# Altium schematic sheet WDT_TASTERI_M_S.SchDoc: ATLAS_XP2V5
size 558 x 431 mm; Organization: IMP Automatika d.o.o.; Revision: V5
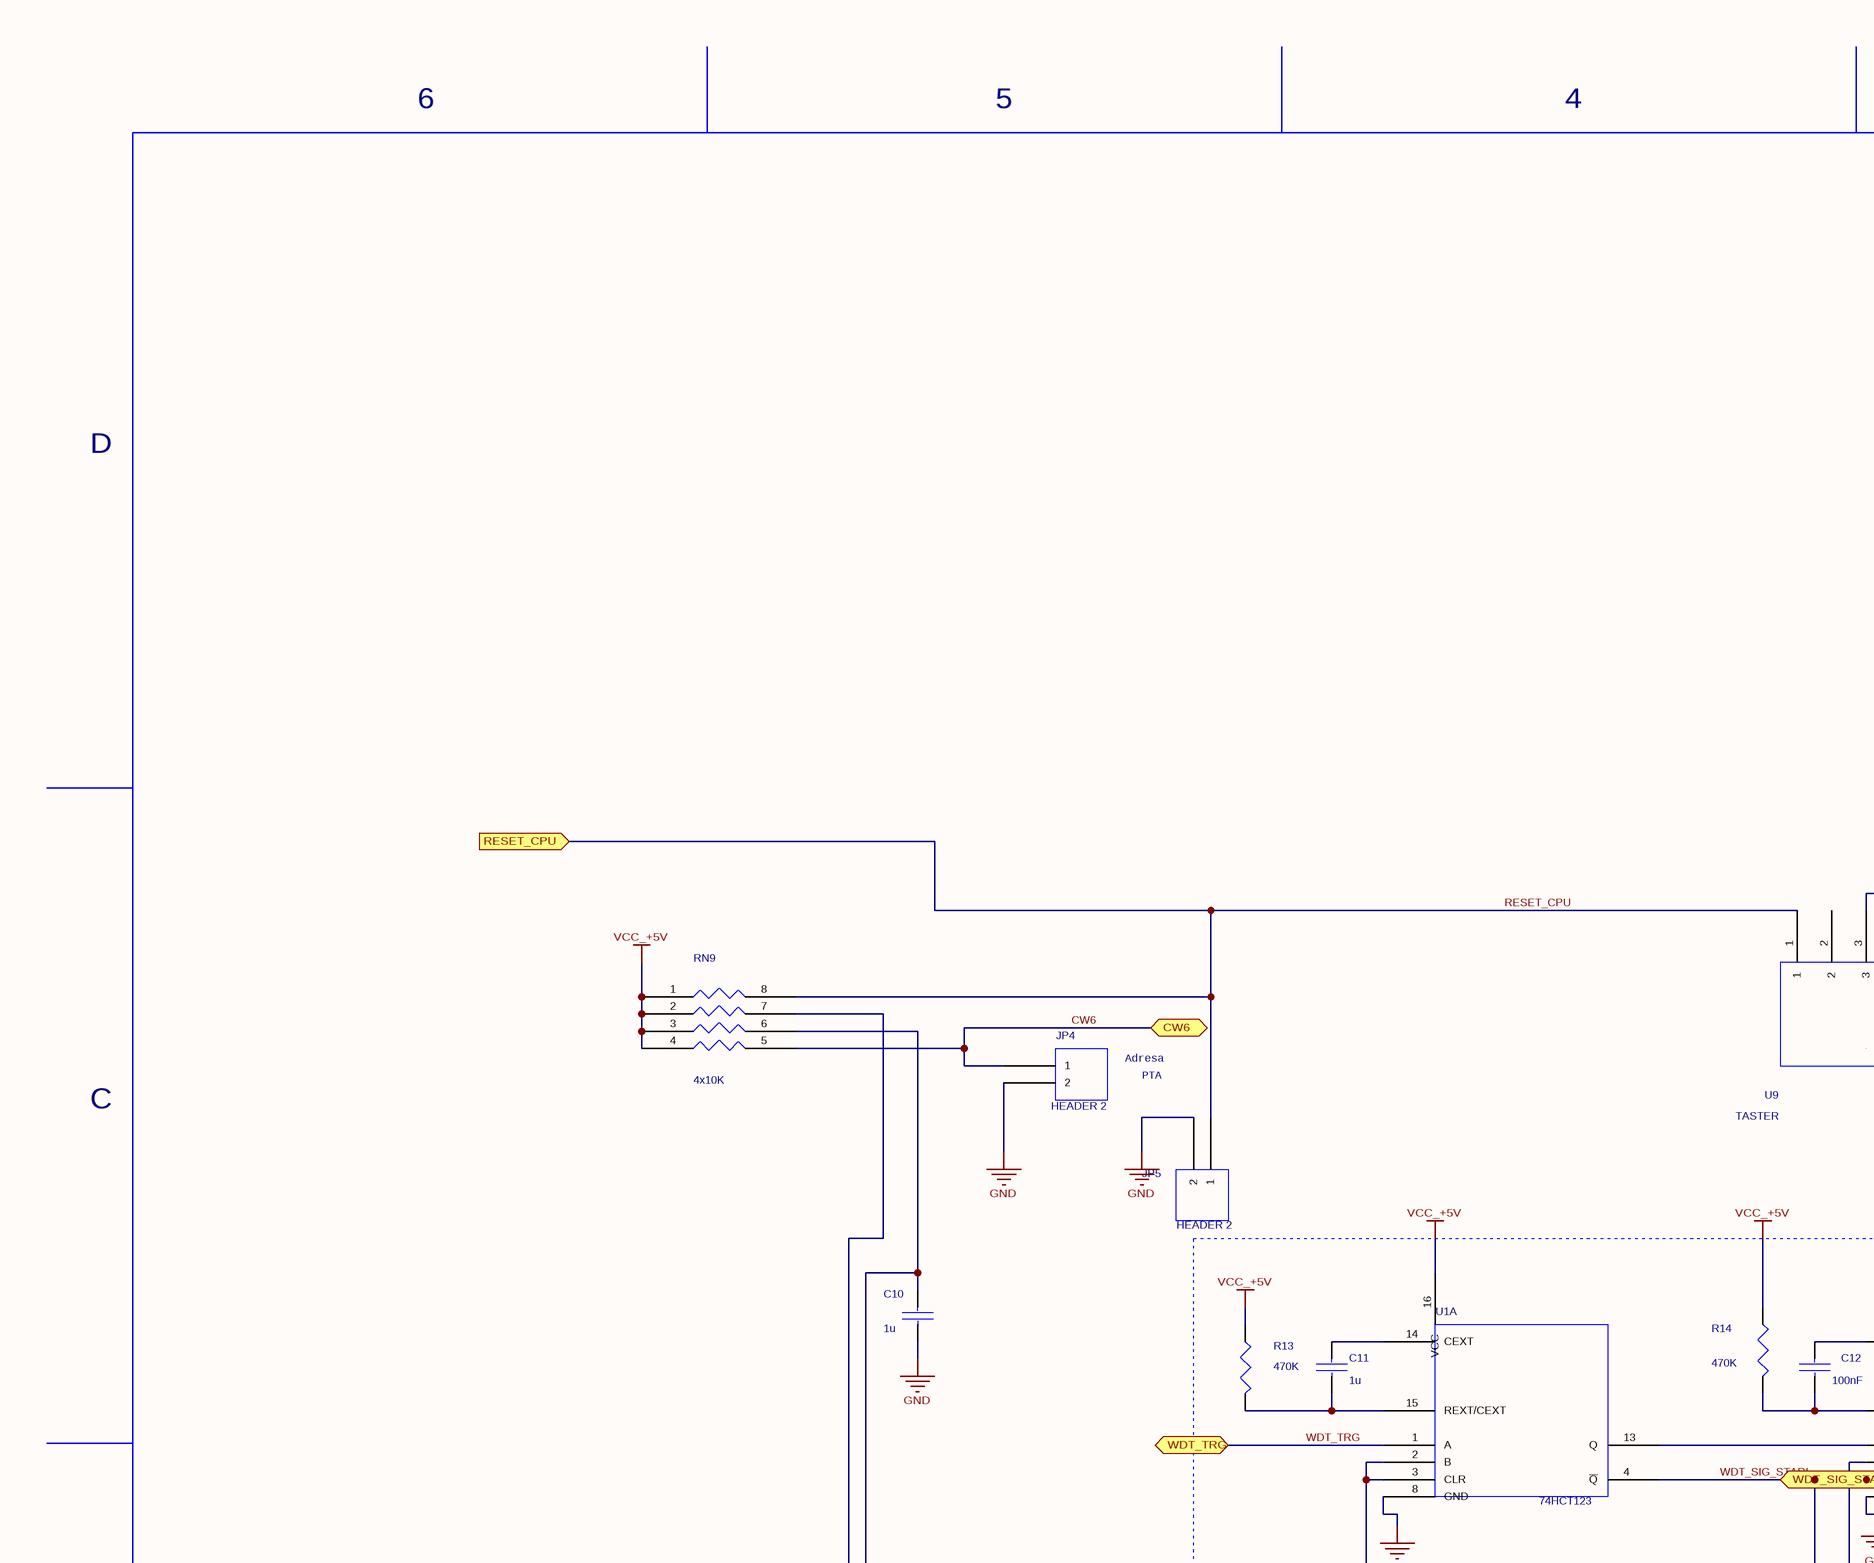
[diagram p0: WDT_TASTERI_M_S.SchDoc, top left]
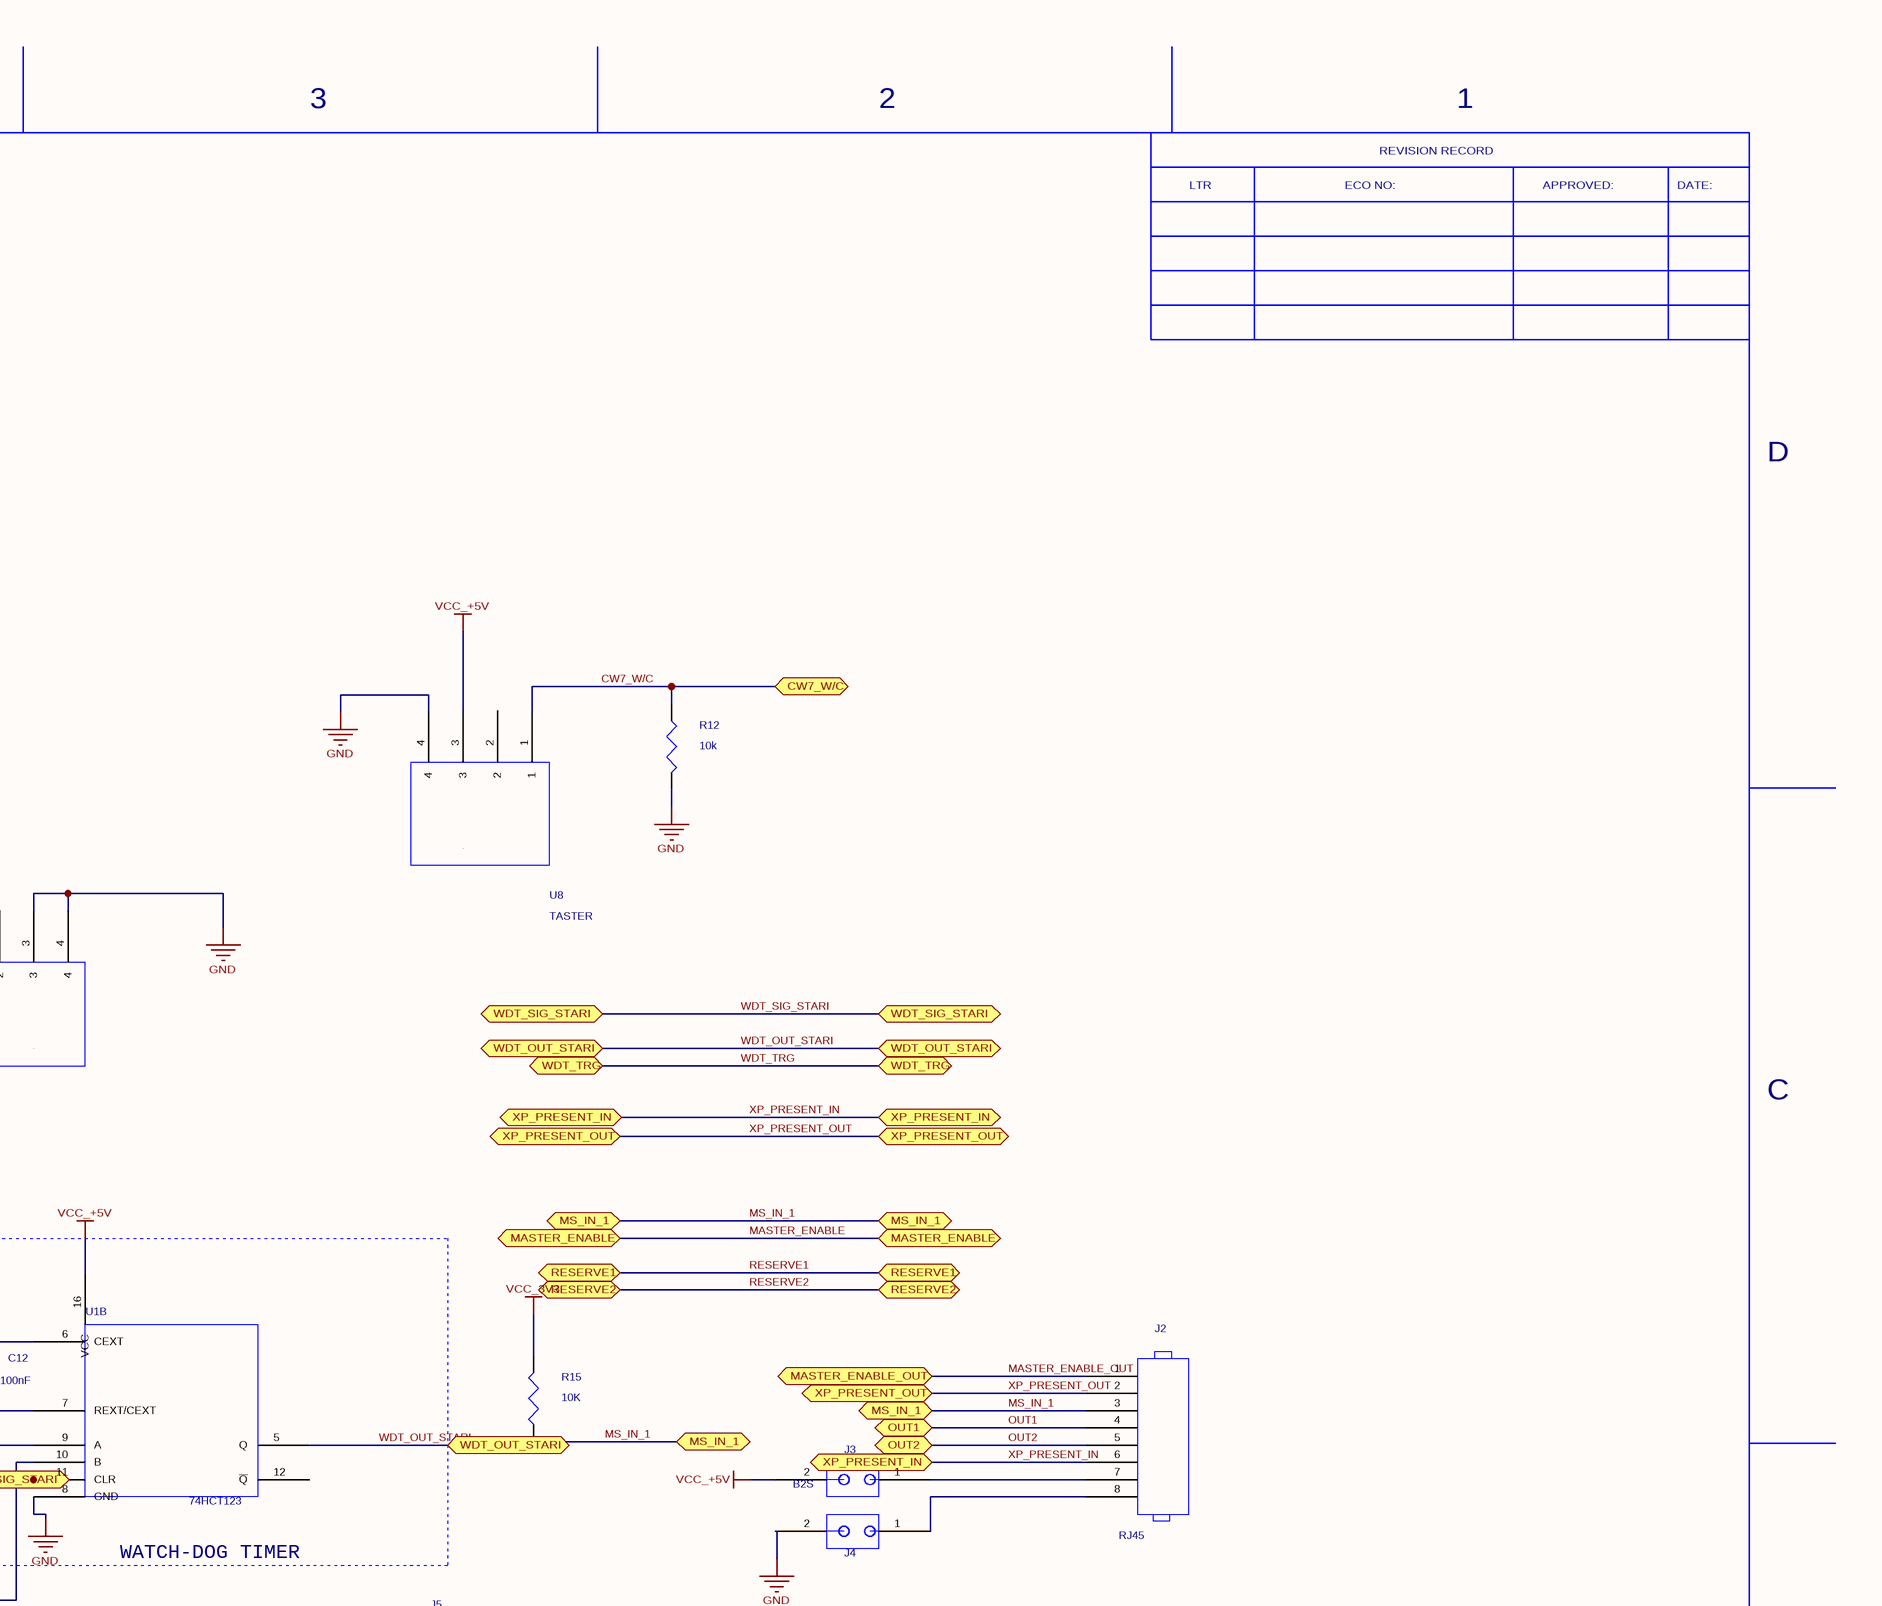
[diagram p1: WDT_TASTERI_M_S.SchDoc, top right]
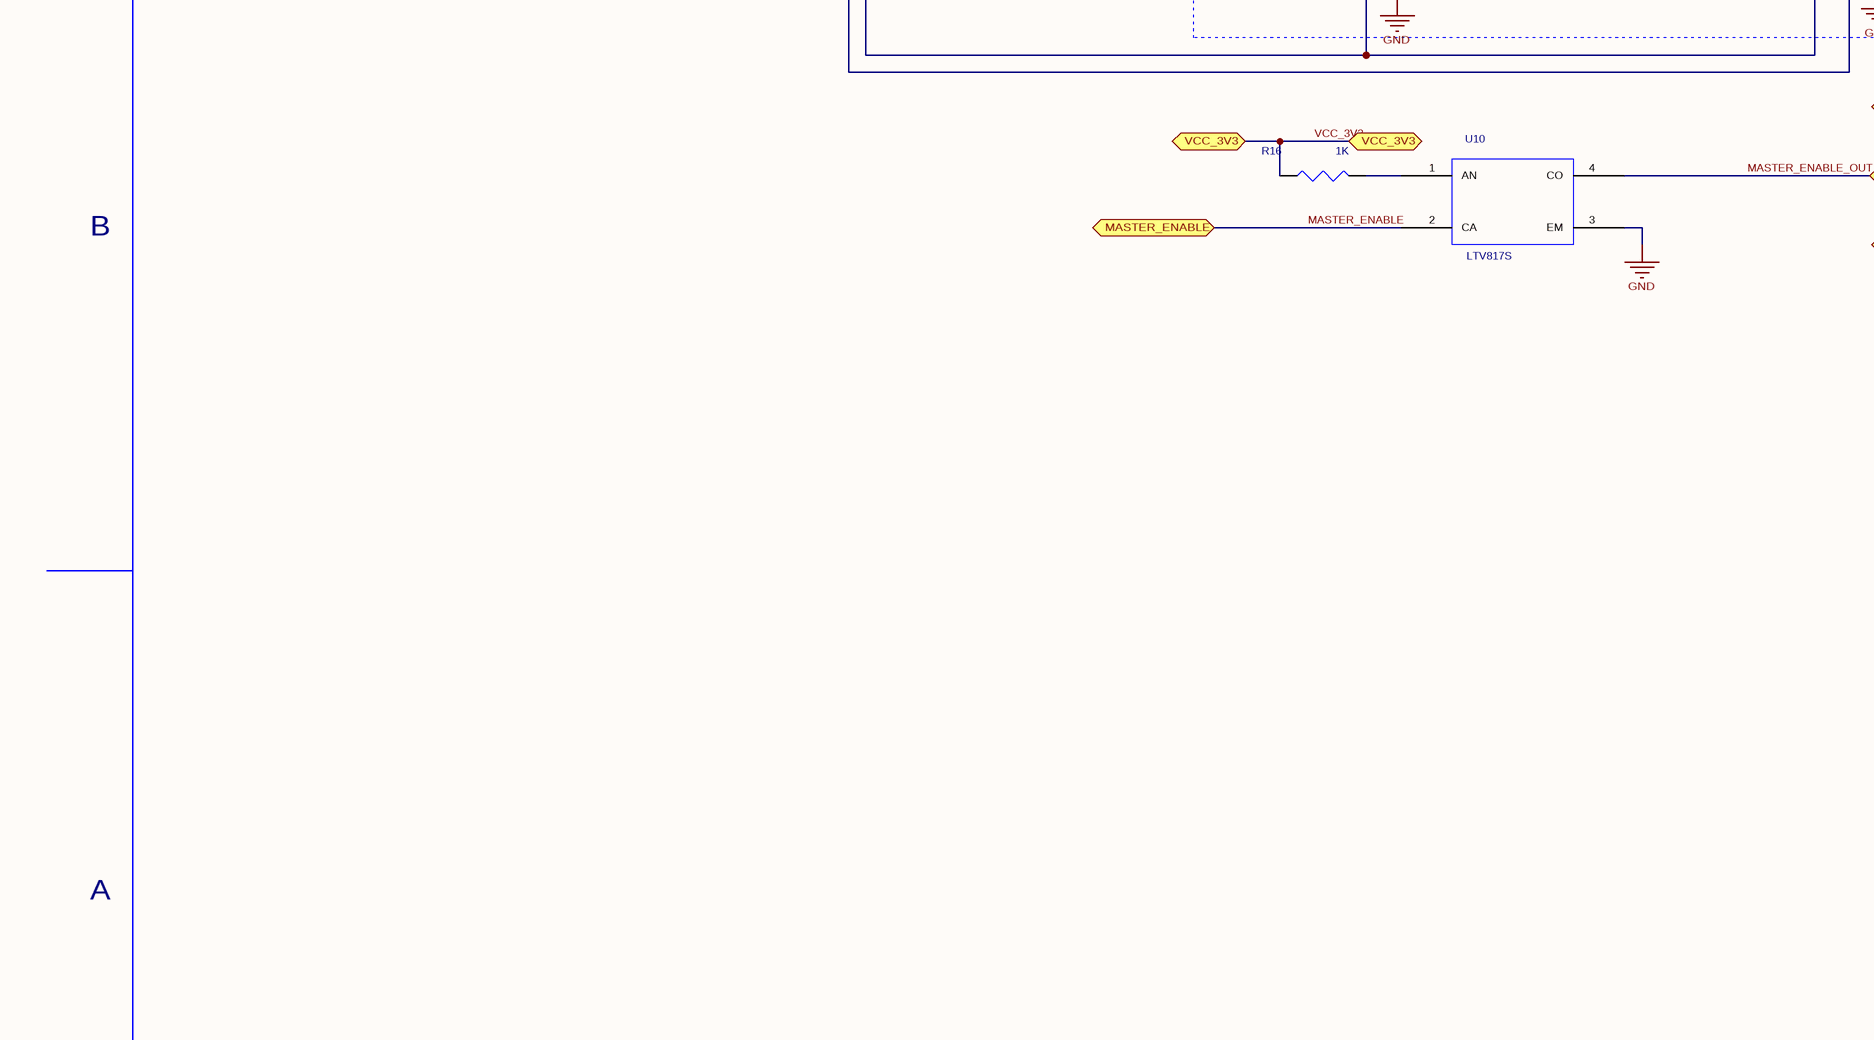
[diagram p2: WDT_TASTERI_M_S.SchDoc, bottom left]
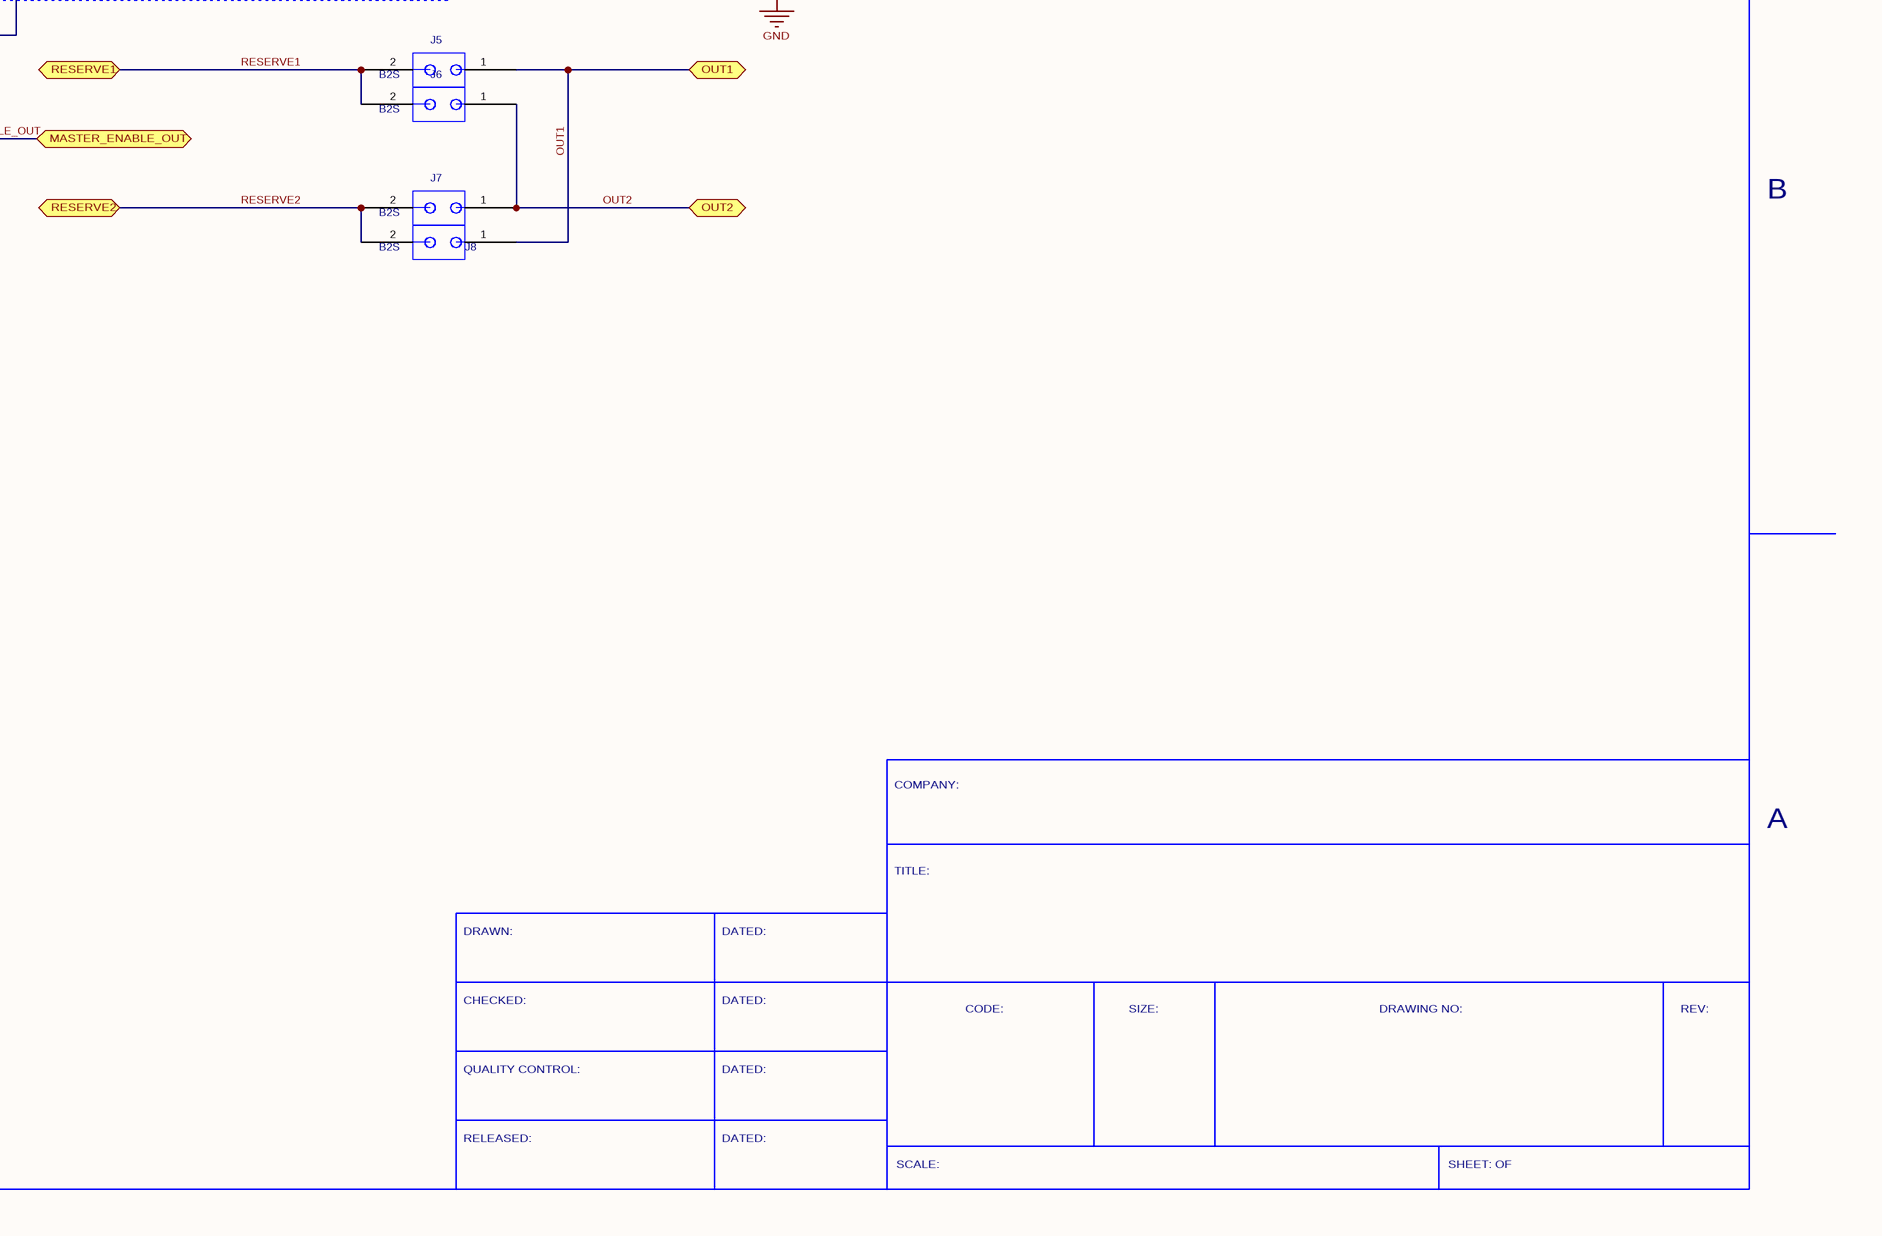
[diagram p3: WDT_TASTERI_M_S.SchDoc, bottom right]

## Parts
C10  value 1u  [SM/C_0805]  (hidden comment: C_2)
C11  value 1u  [SM/C_0805]  (hidden comment: C_2)
C12  value 100nF  [SM/C_0805]  (hidden comment: C_2)
J2  value RJ45  [TELE/TM.420FACE/8X8]  (hidden comment: 8_HEADER)
J3  value B2S  [JUMPER_100]  (hidden comment: B2S_0)
J4  B2S_0  [JUMPER_100]  (value not drawn)
J5  value B2S  [JUMPER_100]  (hidden comment: B2S_0)
J6  value B2S  [JUMPER_100]  (hidden comment: B2S_0)
J7  value B2S  [JUMPER_100]  (hidden comment: B2S_0)
J8  value B2S  [JUMPER_100]  (hidden comment: B2S_0)
JP4  value HEADER 2  [JUMPER_100]  (hidden comment: HEADER_2)
JP5  value HEADER 2  [JUMPER_100]  (hidden comment: HEADER_2)
R12  value 10k  [SM/R_1206]  (hidden comment: RESISTOR_2)
R13  value 470K  [SM/R_1206]  (hidden comment: RESISTOR_2)
R14  value 470K  [SM/R_1206]  (hidden comment: RESISTOR_2)
R15  value 10K  [SM/R_1206]  (hidden comment: RESISTOR_2)
R16  value 1K  [SM/R_1206]  (hidden comment: RESISTOR_2)
RN9  value 4x10K  [SMD_RX4]  (hidden comment: RESAR_IS_4/SM)
U1  value 74HCT123  [SOG.050/16/WG.244/L.375]  (hidden comment: 74HCT123_1)  (parts A,B of 2)
U8  value TASTER  [TP33WW080-SPST_PADS]  (hidden comment: SWITCH_BOJKE)
U9  value TASTER  [TP33WW080-SPST_PADS]  (hidden comment: SWITCH_BOJKE)
U10  value LTV817S  [LTV814S]  (hidden comment: LTV-817)

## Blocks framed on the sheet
WATCH-DOG TIMER: C11 C12 R13 R14 U1

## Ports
CW6 (bidir), CW7_W/C (bidir), MASTER_ENABLE (bidir), MASTER_ENABLE_OUT (bidir), MS_IN_1 (bidir), OUT1 (bidir), OUT2 (bidir), RESERVE1 (bidir), RESERVE2 (bidir), RESET_CPU, VCC_3V3 (bidir), WDT_OUT_STARI (bidir), WDT_SIG_STARI (bidir), WDT_TRG (bidir), XP_PRESENT_IN (bidir), XP_PRESENT_OUT (bidir)

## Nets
GND: C10.2 J4.2 JP4.2 JP5.2 R12.2 U1.8(GND) U8.4 U9.3 U9.4 U10.3(EM)
VCC_3V3: R15.2 R16.1 ; port VCC_3V3
VCC_+5V: J3.2 R13.1 R14.1 RN9.1 RN9.2 RN9.3 RN9.4 U1.16(VCC) U8.3
CW6: JP4.1 RN9.5 ; port CW6
CW7_W/C: R12.1 U8.1 ; port CW7_W/C
MASTER_ENABLE: U10.2(CA) ; port MASTER_ENABLE
MASTER_ENABLE_OUT: J2.1 U10.4(CO) ; port MASTER_ENABLE_OUT
MS_IN_1: J2.3 R15.1 ; port MS_IN_1
OUT1: J2.4 J5.1 J8.1 ; port OUT1
OUT2: J2.5 J6.1 J7.1 ; port OUT2
RESERVE1: J5.2 J6.2 ; port RESERVE1
RESERVE2: J7.2 J8.2 ; port RESERVE2
RESET_CPU: JP5.1 RN9.8 U9.1 ; port RESET_CPU
WDT_OUT_STARI: U1.5(Q) ; port WDT_OUT_STARI
WDT_SIG_STARI: U1.4(~{Q}) ; port WDT_SIG_STARI
WDT_TRG: U1.1(A) ; port WDT_TRG
XP_PRESENT_IN: J2.6 ; port XP_PRESENT_IN
XP_PRESENT_OUT: J2.2 ; port XP_PRESENT_OUT
NetC10_1: C10.1 RN9.6 U1.2(B) U1.3(CLR) U1.11(CLR)
NetC11_1: C11.1 U1.14(CEXT)
NetC11_2: C11.2 R13.2 U1.15(REXT/CEXT)
NetC12_1: C12.1 U1.6(CEXT)
NetC12_2: C12.2 R14.2 U1.7(REXT/CEXT)
NetJ2_7: J2.7 J3.1
NetJ2_8: J2.8 J4.1
NetR16_2: R16.2 U10.1(AN)
NetRN9_7: RN9.7 U1.10(B)
NetU1_9: U1.9(A) U1.13(Q)

Not connected (* = marked no-connect by the designer): U1 12(~{Q}); U8 2; U9 2

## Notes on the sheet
- 6
- 5
- 4
- 3
- 2
- 1
- LTR
- ECO NO:
- REVISION RECORD
- APPROVED:
- DATE:
- D
- Adresa
- C
- PTA
- B
- COMPANY:
- A
- TITLE:
- DRAWN:
- DATED:
- CHECKED:
- CODE:
- SIZE:
- DRAWING NO:
- REV:
- QUALITY CONTROL:
- RELEASED:
- SCALE:
- SHEET: OF

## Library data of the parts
C10-C12 = C_2: Source_Path: D:\ORCADWIN\CAPTURE\PTA\PC2A_00.OLB; SDTSourceLibName: C:\WINDOWS\TEMP\PC2A_00.LIB
J2 = 8_HEADER: Source_Path: C:\CADENCE\PSD_15.1\TOOLS\CAPTURE\LIBRARY\CONNECTOR.OLB
J3 J5-J8 = B2S_0: Source_Path: C:\CADENCE\PSD_15.1\TOOLS\ATLAS_ITA\ATLAS_ITA.DSN
J4 = B2S_0: Source_Path: C:\CADENCE\PSD_15.1\TOOLS\ATLAS_ITA\ATLAS_ITA.DSN; Value: B2S
JP4 JP5 = HEADER_2: Source_Path: D:\ORCADWIN\CAPTURE\PTA\PC2A_00.OLB; SDTSourceLibName: C:\WINDOWS\TEMP\PC2A_00.LIB
R12-R16 = RESISTOR_2: Source_Path: C:\CADENCE\PSD_15.1\TOOLS\CAPTURE\LIBRARY\DISCRETE.OLB
RN9 = RESAR_IS_4/SM: Source_Path: C:\ORCAD\ORCAD_10.5\TOOLS\CAPTURE\LIBRARY\DISCRETE.OLB
U1 = 74HCT123_1: Source_Path: E:\MILOS\PROJECTS\ATLAS_XP\ATLAS_XP.DSN; SDTSourceLibName: C:\WINDOWS\TEMP\PC2A_00.LIB
U8 = SWITCH_BOJKE: CW_TASTER; Source_Path: C:\CADENCE\PSD_15.1\TOOLS\ATLAS_ITA\LIBRARY1.OLB; Serial No: TP33WW080; Geometry.Height: 8.65mm
U9 = SWITCH_BOJKE: RST_TASTER; Source_Path: C:\CADENCE\PSD_15.1\TOOLS\ATLAS_ITA\LIBRARY1.OLB; Serial No: TP33WW080; Geometry.Height: 8.65mm
U10 = LTV-817: Source_Path: C:\PROJECTS\ATLAS_XP\LIBRARY1.OLB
